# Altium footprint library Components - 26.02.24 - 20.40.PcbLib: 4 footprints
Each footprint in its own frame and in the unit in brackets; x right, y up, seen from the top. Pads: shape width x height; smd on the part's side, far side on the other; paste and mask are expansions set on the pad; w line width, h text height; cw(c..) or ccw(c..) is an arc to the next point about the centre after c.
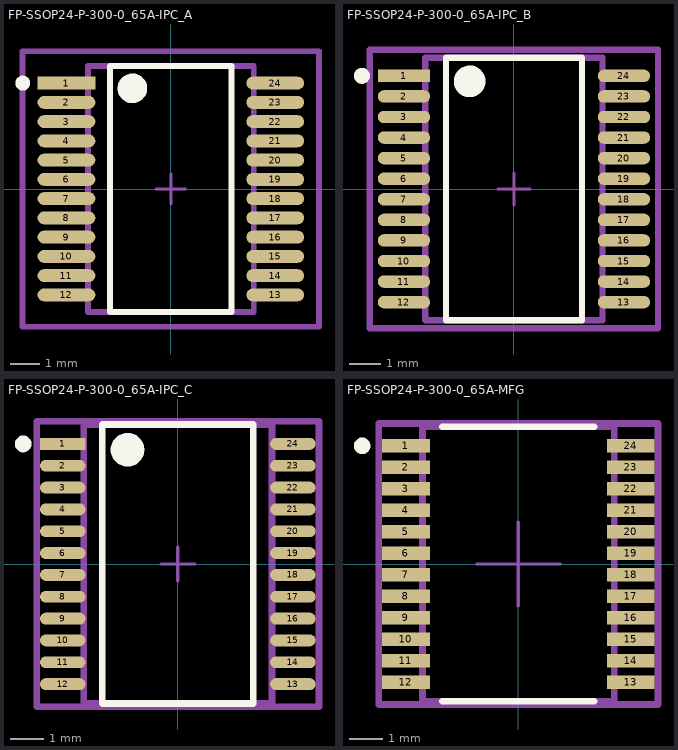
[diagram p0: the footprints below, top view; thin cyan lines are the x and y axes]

## FP-SSOP24-P-300-0_65A-IPC_A [mm]
pads (24):
  rect 1.954x0.432 smd paste+0 mask+0: 1(-3.525,3.575)
  rrect100% 1.954x0.432 smd paste+0 mask+0: 2(-3.525,2.925) 3(-3.525,2.275) 4(-3.525,1.625) 5(-3.525,0.975) 6(-3.525,0.325) 7(-3.525,-0.325) 8(-3.525,-0.975) 9(-3.525,-1.625) 10(-3.525,-2.275) 11(-3.525,-2.925) 12(-3.525,-3.575) 13(3.525,-3.575) 14(3.525,-2.925) 15(3.525,-2.275) 16(3.525,-1.625) 17(3.525,-0.975) 18(3.525,-0.325) 19(3.525,0.325) 20(3.525,0.975) 21(3.525,1.625) 22(3.525,2.275) 23(3.525,2.925) 24(3.525,3.575)
Top Overlay:
  circle w0.5: c-1.298,3.4 r0.25
  circle w0.25: c-5.002,3.575 r0.125
  lines w0.2: -2.048,-4.15 2.048,-4.15 2.048,4.15 -2.048,4.15 -2.048,-4.15
Top Assembly:
  lines w0.2: -5.002,-4.65 5.002,-4.65 5.002,4.65 -5.002,4.65 -5.002,-4.65
  text ".Designator" at 0,0.188 h1
Top 3D Body:
  lines w0.2: -2.8,-4.15 2.8,-4.15 2.8,4.15 -2.8,4.15 -2.8,-4.15
Top Courtyard:
  lines w0.2: -5.002,-4.65 5.002,-4.65 5.002,4.65 -5.002,4.65 -5.002,-4.65
Top Component Center:
  lines w0.1: -0.5,0 0.5,0 ; 0,-0.5 0,0.5
3D body "IC_Toshiba_TB6612FNG_C_8_EL_eec.STEP": height 0.25, standoff 0, extent -5.002,-4.65 5.002,4.65

## FP-SSOP24-P-300-0_65A-IPC_B [mm]
pads (24):
  rect 1.654x0.392 smd paste+0 mask+0: 1(-3.475,3.575)
  rrect100% 1.654x0.392 smd paste+0 mask+0: 2(-3.475,2.925) 3(-3.475,2.275) 4(-3.475,1.625) 5(-3.475,0.975) 6(-3.475,0.325) 7(-3.475,-0.325) 8(-3.475,-0.975) 9(-3.475,-1.625) 10(-3.475,-2.275) 11(-3.475,-2.925) 12(-3.475,-3.575) 13(3.475,-3.575) 14(3.475,-2.925) 15(3.475,-2.275) 16(3.475,-1.625) 17(3.475,-0.975) 18(3.475,-0.325) 19(3.475,0.325) 20(3.475,0.975) 21(3.475,1.625) 22(3.475,2.275) 23(3.475,2.925) 24(3.475,3.575)
Top Overlay:
  circle w0.5: c-1.398,3.4 r0.25
  circle w0.25: c-4.802,3.575 r0.125
  lines w0.2: -2.148,-4.15 2.148,-4.15 2.148,4.15 -2.148,4.15 -2.148,-4.15
Top Assembly:
  lines w0.2: -4.552,-4.4 4.552,-4.4 4.552,4.4 -4.552,4.4 -4.552,-4.4
  text ".Designator" at 0,0.188 h1
Top 3D Body:
  lines w0.2: -2.8,-4.15 2.8,-4.15 2.8,4.15 -2.8,4.15 -2.8,-4.15
Top Courtyard:
  lines w0.2: -4.552,-4.4 4.552,-4.4 4.552,4.4 -4.552,4.4 -4.552,-4.4
Top Component Center:
  lines w0.1: -0.5,0 0.5,0 ; 0,-0.5 0,0.5
3D body "IC_Toshiba_TB6612FNG_C_8_EL_eec.STEP": height 0.25, standoff 0, extent -4.552,-4.4 4.552,4.4

## FP-SSOP24-P-300-0_65A-IPC_C [mm]
pads (24):
  rect 1.354x0.352 smd paste+0 mask+0: 1(-3.425,3.575)
  rrect100% 1.354x0.352 smd paste+0 mask+0: 2(-3.425,2.925) 3(-3.425,2.275) 4(-3.425,1.625) 5(-3.425,0.975) 6(-3.425,0.325) 7(-3.425,-0.325) 8(-3.425,-0.975) 9(-3.425,-1.625) 10(-3.425,-2.275) 11(-3.425,-2.925) 12(-3.425,-3.575) 13(3.425,-3.575) 14(3.425,-2.925) 15(3.425,-2.275) 16(3.425,-1.625) 17(3.425,-0.975) 18(3.425,-0.325) 19(3.425,0.325) 20(3.425,0.975) 21(3.425,1.625) 22(3.425,2.275) 23(3.425,2.925) 24(3.425,3.575)
Top Overlay:
  circle w0.5: c-1.498,3.4 r0.25
  circle w0.25: c-4.602,3.575 r0.125
  lines w0.2: -2.248,-4.15 2.248,-4.15 2.248,4.15 -2.248,4.15 -2.248,-4.15
Top Assembly:
  lines w0.2: -4.202,-4.25 4.202,-4.25 4.202,4.25 -4.202,4.25 -4.202,-4.25
  text ".Designator" at 0,0.188 h1
Top 3D Body:
  lines w0.2: -2.8,-4.15 2.8,-4.15 2.8,4.15 -2.8,4.15 -2.8,-4.15
Top Courtyard:
  lines w0.2: -4.202,-4.25 4.202,-4.25 4.202,4.25 -4.202,4.25 -4.202,-4.25
Top Component Center:
  lines w0.1: -0.5,0 0.5,0 ; 0,-0.5 0,0.5
3D body "IC_Toshiba_TB6612FNG_C_8_EL_eec.STEP": height 0.25, standoff 0, extent -4.202,-4.25 4.202,4.25

## FP-SSOP24-P-300-0_65A-MFG [mm]
pads (24):
  rect 1.45x0.4 smd paste+0 mask+0: 1(-3.4,3.575) 2(-3.4,2.925) 3(-3.4,2.275) 4(-3.4,1.625) 5(-3.4,0.975) 6(-3.4,0.325) 7(-3.4,-0.325) 8(-3.4,-0.975) 9(-3.4,-1.625) 10(-3.4,-2.275) 11(-3.4,-2.925) 12(-3.4,-3.575) 13(3.4,-3.575) 14(3.4,-2.925) 15(3.4,-2.275) 16(3.4,-1.625) 17(3.4,-0.975) 18(3.4,-0.325) 19(3.4,0.325) 20(3.4,0.975) 21(3.4,1.625) 22(3.4,2.275) 23(3.4,2.925) 24(3.4,3.575)
Top Overlay:
  circle w0.25: c-4.725,3.575 r0.125
  lines w0.2: -2.3,-4.15 2.3,-4.15 ; -2.3,4.15 2.3,4.15
Top Assembly:
  lines w0.2: -4.225,-4.25 4.225,-4.25 4.225,4.25 -4.225,4.25 -4.225,-4.25
  text ".Designator" at 0,0.188 h1
Top 3D Body:
  lines w0.2: -2.9,-4.15 2.9,-4.15 2.9,4.15 -2.9,4.15 -2.9,-4.15
Top Courtyard:
  lines w0.2: -4.225,-4.25 4.225,-4.25 4.225,4.25 -4.225,4.25 -4.225,-4.25
Top Component Center:
  lines w0.1: -1.268,0 1.268,0 ; 0,-1.268 0,1.268
3D body "IC_Toshiba_TB6612FNG_C_8_EL_eec.STEP": height 0.25, standoff 0, extent -4.225,-4.25 4.225,4.25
